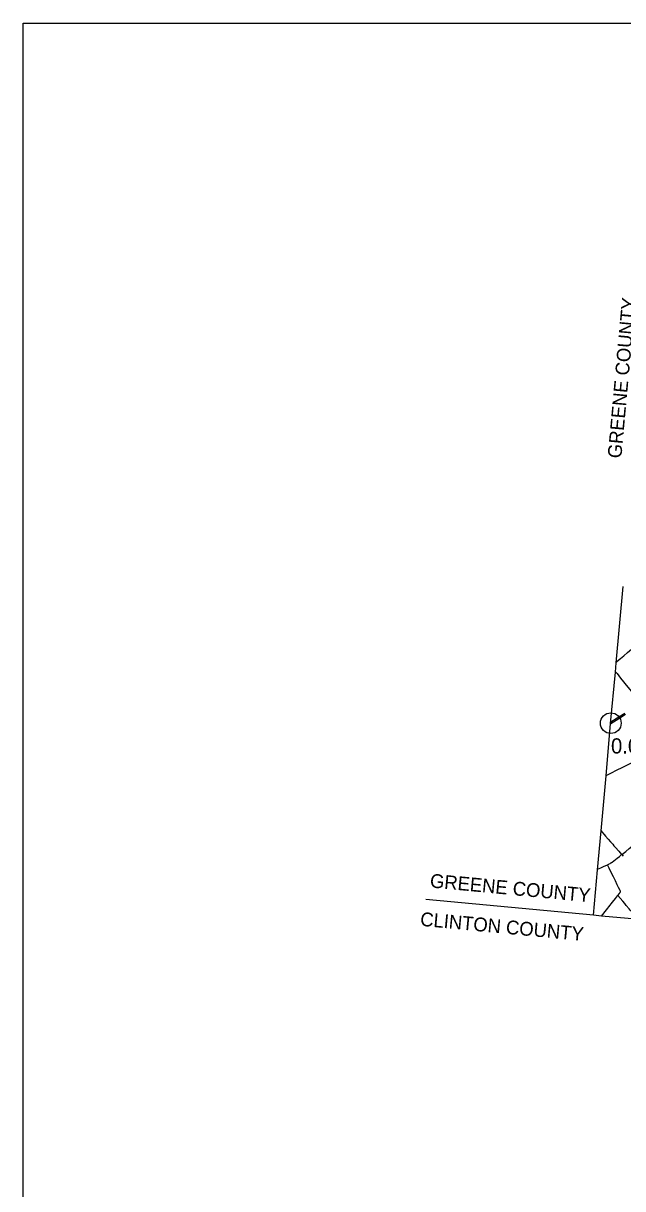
# Model space of a CAD drawing. Extents: x 1597222 to 1925846, y 496284 to 911751.
# Drawn here: x 1597222 to 1640665, y 546977 to 631367 of the extents above; entities that cross this region are included whole.
import ezdxf

# ---------------------------------------------------------------- set-up
doc = ezdxf.new("R2010")
doc.units = 0
for name, color, linetype in [('Default', 7, 'Continuous'), ('GM_X_Adjacent_County', 7, 'Continuous'), ('GM_X_Adjacent_County_Text', 7, 'Continuous'), ('GM_X_County', 7, 'Continuous'), ('GM_X_County_Road', 7, 'Continuous'), ('GM_X_Interstate_Route', 7, 'Continuous'), ('GM_X_Township', 7, 'Continuous'), ('GM_X_Township_Road', 7, 'Continuous'), ('SC_Scratch1', 7, 'Continuous')]:
    doc.layers.add(name, color=color, linetype=linetype)

msp = doc.modelspace()

# ---------------------------------------------------------------- linework, layer by layer
at = {"layer": 'Default'}
msp.add_circle((1639802, 580687), 750, dxfattribs=at)
msp.add_circle((1639802, 580687), 750, dxfattribs=at)
at = {"layer": 'GM_X_Adjacent_County'}
msp.add_line((1638543, 566777), (1626403, 567912), dxfattribs=at)
at = {"layer": 'GM_X_County'}
msp.add_lwpolyline([(1641608, 566488), (1639127, 566722), (1638543, 566777), (1638842, 570076), (1639097, 572897), (1639456, 576867), (1639791, 580666), (1640135, 584378), (1640197, 585063), (1640696, 590579)], dxfattribs=at)
at = {"layer": 'GM_X_County_Road'}
for points in [[(1640205, 585127), (1640411, 585299), (1640499, 585372), (1640738, 585572), (1641014, 585805), (1641165, 585931), (1641645, 586329), (1642123, 586728), (1642513, 587055), (1642651, 587171), (1642967, 587433), (1643193, 587622), (1643344, 587748), (1643608, 587969), (1643974, 588273), (1644201, 588463), (1644653, 588842), (1645031, 589157), (1645258, 589346), (1645812, 589809), (1645976, 589944), (1646026, 589987), (1646060, 590022), (1646064, 590026)], [(1640143, 584415), (1640177, 584371), (1640256, 584275), (1640511, 583955), (1641045, 583289), (1641301, 582969), (1641516, 582700), (1641659, 582520), (1641761, 582394), (1641937, 582176), (1641966, 582139), (1642025, 582065), (1642121, 581945), (1642233, 581804), (1642357, 581651), (1642736, 581176), (1643064, 580767), (1643290, 580485), (1643689, 579986), (1643967, 579641), (1644121, 579449), (1644228, 579317)], [(1639462, 576901), (1639859, 577100), (1640226, 577284), (1640665, 577504), (1641016, 577682), (1641631, 577993), (1642115, 578234), (1642453, 578402), (1642657, 578507), (1642848, 578603), (1643066, 578716), (1643534, 578954), (1643797, 579087), (1644147, 579268), (1644190, 579292), (1644228, 579317)], [(1640591, 571169), (1640886, 571403), (1641143, 571607), (1641477, 571872), (1641696, 572046), (1641902, 572209), (1642095, 572362), (1642364, 572577), (1642493, 572678), (1642775, 572904), (1642995, 573076), (1643200, 573240), (1643856, 573761), (1644036, 573904), (1644190, 574027), (1644420, 574212), (1644824, 574535)], [(1639555, 570438), (1639637, 570477), (1639756, 570532), (1639786, 570547), (1639814, 570562), (1639836, 570575), (1639856, 570588), (1639881, 570606), (1639909, 570626), (1640013, 570707), (1640271, 570911), (1640437, 571044), (1640564, 571148), (1640591, 571169)], [(1638847, 570109), (1639074, 570211), (1639267, 570299), (1639555, 570438)]]:
    msp.add_lwpolyline(points, dxfattribs=at)
at = {"layer": 'GM_X_Interstate_Route'}
for points in [[(1639802, 580656), (1640183, 580904), (1640521, 581119), (1640865, 581336)], [(1639814, 580787), (1640263, 581066), (1640808, 581409)]]:
    msp.add_lwpolyline(points, dxfattribs=at)
at = {"layer": 'GM_X_Township'}
msp.add_lwpolyline([(1641608, 566488), (1639127, 566722), (1638543, 566777)], dxfattribs=at)
at = {"layer": 'GM_X_Township_Road'}
for points in [[(1639099, 572885), (1639148, 572830), (1639318, 572636), (1639426, 572512), (1639619, 572288), (1639792, 572090), (1639942, 571917), (1640028, 571817), (1640135, 571693), (1640372, 571421), (1640470, 571310), (1640587, 571173), (1640591, 571169)], [(1640591, 571169), (1640695, 571049)], [(1640312, 568219), (1640427, 568361), (1640468, 568412), (1640486, 568439), (1640494, 568454), (1640500, 568469), (1640503, 568485), (1640504, 568501), (1640502, 568517), (1640498, 568533), (1640485, 568564), (1640368, 568799), (1640273, 568990), (1640134, 569269), (1639988, 569563), (1639835, 569872), (1639681, 570180), (1639586, 570371), (1639558, 570433), (1639555, 570438)], [(1639131, 566723), (1639217, 566828), (1639400, 567060), (1639584, 567291), (1639654, 567382), (1639918, 567717), (1640141, 568001), (1640292, 568195), (1640312, 568219)], [(1641650, 566485), (1641591, 566556), (1641516, 566642), (1641452, 566717), (1641422, 566756), (1641404, 566784), (1641397, 566798), (1641391, 566813), (1641386, 566829), (1641382, 566845), (1641376, 566894), (1641371, 566926), (1641361, 566957), (1641354, 566972), (1641346, 566986), (1641327, 567012), (1641306, 567038), (1641209, 567149), (1641125, 567250), (1640924, 567488), (1640808, 567626), (1640672, 567790), (1640314, 568216), (1640312, 568219)]]:
    msp.add_lwpolyline(points, dxfattribs=at)
at = {"layer": 'SC_Scratch1'}
msp.add_lwpolyline([(1597222, 631367), (1793472, 631367), (1793472, 496867), (1597222, 496867)], close=True, dxfattribs=at)

# ---------------------------------------------------------------- texts
at = {"layer": 'Default'}
msp.add_text('0.00', height=1100, dxfattribs=at).set_placement((1639816, 578490))
msp.add_text('0.00', height=1100, dxfattribs=at).set_placement((1639816, 578490))
at = {"layer": 'GM_X_Adjacent_County_Text'}
for s, rotation, p in [('GREENE COUNTY', 84.81669, (1640562, 599835)), ('GREENE COUNTY', 354.68715, (1626665, 568798)), ('CLINTON COUNTY', 354.65079, (1625956, 566020))]:
    msp.add_text(s, height=1000, rotation=rotation, dxfattribs=at).set_placement(p)

doc.saveas('drawing.dxf')
